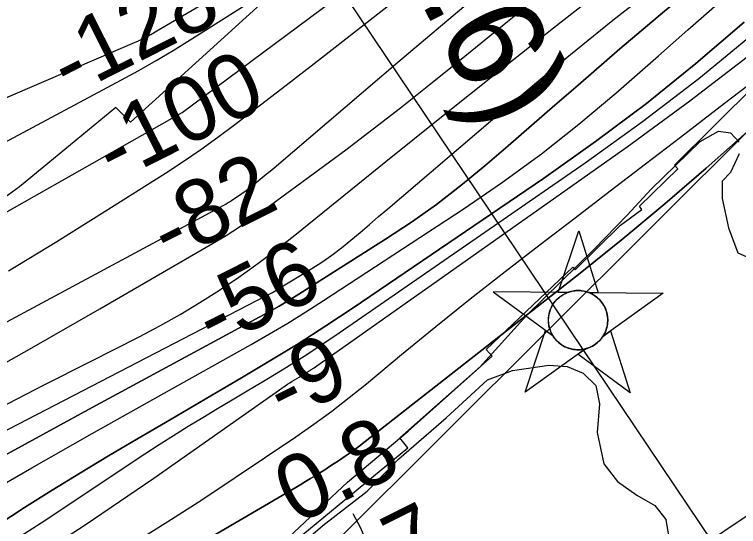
# Model space of a CAD drawing. Extents: x 3715084 to 3753216, y 488173 to 513963.
# Drawn here: x 3731429 to 3732175, y 498790 to 499318 of the extents above; entities that cross this region are included whole.
import ezdxf

# ---------------------------------------------------------------- set-up
doc = ezdxf.new("R2010")
doc.units = 0
for name, color, linetype in [('V-CHAN-NAID', 7, 'Continuous'), ('V-RIVR-EDGE', 7, 'Continuous'), ('V-RIVR-RANG', 7, 'Continuous'), ('V-ROAD-CNTR', 7, 'Continuous'), ('V-RRAP-FSHR', 7, 'Continuous'), ('V-RRAP-RVMT', 7, 'Continuous'), ('V-SITE-VEGE', 7, 'Continuous'), ('V-TOPO-DPTH', 7, 'Continuous'), ('V-TOPO-MAJR', 7, 'Continuous'), ('V-TOPO-MINR', 7, 'Continuous'), ('V-TOPO-WATR', 7, 'Continuous')]:
    doc.layers.add(name, color=color, linetype=linetype)

msp = doc.modelspace()

# ---------------------------------------------------------------- linework, layer by layer
at = {"layer": 'V-CHAN-NAID'}
for points in [[(3731998.934, 499031.306), (3731989.347, 499031.374), (3732010.473, 499094.858), (3732030.697, 499031.081), (3732021.11, 499031.14900000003), (3732019.5330000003, 499031.727), (3732017.438, 499032.347), (3732015.398, 499032.798), (3732013.362, 499033.106), (3732012.1950000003, 499033.22000000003), (3732010.661, 499033.30100000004), (3732008.9390000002, 499033.299), (3732007.569, 499033.229), (3732005.663, 499033.028), (3732004.2970000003, 499032.809), (3732002.5130000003, 499032.425), (3732000.983, 499032.005), (3731999.951, 499031.674)], [(3731998.934, 499031.306), (3731922.443, 499031.848), (3731984.008, 498986.449), (3731982.895, 498988.358), (3731982.085, 498989.98600000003), (3731981.2600000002, 498991.954), (3731980.5640000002, 498994.00800000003), (3731980.199, 498995.331), (3731979.838, 498996.957), (3731979.594, 498998.402), (3731979.406, 499000), (3731979.2970000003, 499001.73600000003), (3731979.285, 499003.31700000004), (3731979.392, 499005.391), (3731979.575, 499007.009), (3731979.967, 499009.212), (3731980.448, 499011.135), (3731981.051, 499013.022), (3731981.7060000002, 499014.701), (3731982.433, 499016.289), (3731983.247, 499017.824), (3731984.308, 499019.561), (3731985.339, 499021.031), (3731986.339, 499022.3), (3731987.341, 499023.446), (3731988.65, 499024.783), (3731989.701, 499025.748), (3731991.418, 499027.145), (3731992.63, 499028.015), (3731994.3170000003, 499029.085), (3731996.048, 499030.03), (3731997.494, 499030.71400000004)], [(3732021.11, 499031.14900000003), (3732097.602, 499030.606), (3732035.399, 498986.08400000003), (3732036.31, 498987.57300000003), (3732037.288, 498989.42), (3732038.003, 498991.005), (3732038.742, 498992.96), (3732039.287, 498994.745), (3732039.685, 498996.384), (3732040.046, 498998.39400000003), (3732040.2320000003, 498999.967), (3732040.356, 499002.173), (3732040.326, 499004.235), (3732040.1380000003, 499006.455), (3732039.872, 499008.213), (3732039.381, 499010.445), (3732038.741, 499012.585), (3732037.991, 499014.56700000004), (3732037.343, 499016.01), (3732036.336, 499017.92600000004), (3732035.274, 499019.648), (3732034.06, 499021.35000000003), (3732032.799, 499022.889), (3732031.5270000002, 499024.255), (3732029.895, 499025.787), (3732028.1520000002, 499027.199), (3732026.469, 499028.376), (3732024.582, 499029.50800000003), (3732023.11, 499030.26900000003)], [(3732017.3680000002, 498973.178), (3731955.165, 498928.656), (3731976.291, 498992.139), (3731984.008, 498986.449), (3731984.643, 498985.485), (3731986.026, 498983.626), (3731987.239, 498982.21), (3731988.705, 498980.707), (3731990.094, 498979.456), (3731991.548, 498978.3), (3731992.951, 498977.313), (3731994.629, 498976.277), (3731996.343, 498975.36600000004), (3731998.134, 498974.555), (3731999.58, 498973.999), (3732001.208, 498973.47000000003), (3732003.434, 498972.906), (3732004.966, 498972.619), (3732006.991, 498972.362), (3732008.528, 498972.25800000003), (3732010.389, 498972.23600000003), (3732012.078, 498972.314), (3732013.788, 498972.49), (3732015.69, 498972.80100000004)], [(3732035.399, 498986.08400000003), (3732043.1950000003, 498991.66500000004), (3732063.419, 498927.88800000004), (3732009.571, 498967.598), (3732017.3680000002, 498973.178), (3732019.034, 498973.65400000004), (3732020.646, 498974.21400000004), (3732022.804, 498975.128), (3732024.539, 498976.012), (3732026.4050000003, 498977.126), (3732028.144, 498978.338), (3732029.696, 498979.583), (3732030.983, 498980.751), (3732032.367, 498982.17100000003), (3732033.571, 498983.57300000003), (3732034.69, 498985.045)]]:
    msp.add_lwpolyline(points, close=True, dxfattribs=at)
msp.add_circle((3732009.820163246, 499002.7718519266), 30.540600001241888, dxfattribs=at)
at = {"layer": 'V-RIVR-EDGE'}
for points in [[(3731689.8314078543, 498758.2833762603), (3731772.267144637, 498835.5216719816), (3731834.831362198, 498888.19571232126), (3731908.2340504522, 498954.0501381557), (3731956.993808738, 499007.95896622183), (3732026.8004969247, 499076.223590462), (3732060.5046795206, 499110.9591943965), (3732085.184720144, 499137.91286621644), (3732135.733571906, 499187.01465730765), (3732154.370303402, 499197.7744534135), (3732166.972632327, 499195.94231157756), (3732175.953725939, 499186.31487779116)], [(3732175.9240374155, 499174.30841854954), (3732166.871691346, 499155.12035015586), (3732158.4449034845, 499146.13628769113), (3732158.400370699, 499128.1265988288), (3732164.929701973, 499098.0941220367), (3732174.47103904, 499072.2564838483), (3732192.461430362, 499064.4077525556)]]:
    msp.add_lwpolyline(points, dxfattribs=at)
at = {"layer": 'V-RIVR-RANG'}
msp.add_line((3732171.634, 498739.5240000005), (3731602.801, 499586.1890000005), dxfattribs=at)
at = {"layer": 'V-ROAD-CNTR'}
msp.add_lwpolyline([(3731869.65422165, 498539.2948953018), (3731864.162232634, 498549.95487398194), (3731854.753251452, 498570.33883321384), (3731844.896271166, 498591.65479058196), (3731838.012284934, 498602.94376800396), (3731835.38929018, 498607.3817591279), (3731833.8952931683, 498610.87875213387), (3731829.838301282, 498629.54371480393), (3731826.18430859, 498650.1526735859), (3731820.0663208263, 498676.32262124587), (3731813.5783338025, 498702.2205694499), (3731807.666345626, 498723.18452752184), (3731801.545357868, 498743.9584859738), (3731797.231366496, 498757.9214580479), (3731792.5453758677, 498772.2724293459), (3731786.0043889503, 498788.10939767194), (3731778.115404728, 498802.88936811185)], dxfattribs=at)
at = {"layer": 'V-RRAP-FSHR'}
for points in [[(3728004.355522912, 498122.759115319), (3728249.570755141, 498078.76397927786), (3728561.470915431, 498063.71117926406), (3728941.9278757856, 498053.3667312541), (3729895.3271726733, 498086.10810728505), (3730231.158212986, 498125.41537132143), (3730543.470021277, 498170.09453936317), (3730885.5146935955, 498262.3692274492), (3731364.1691580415, 498511.07834768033), (3731760.7561664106, 498774.8320759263), (3732302.403014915, 499315.13748442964), (3732839.9006154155, 499636.89057272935)], [(3732355.051, 498904.53500000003), (3732342.347, 498883.342), (3732313.9590000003, 498861.691), (3732243.934, 498823.59), (3732183.048, 498800.223), (3732137.92, 498769.938), (3732085.916, 498726.516), (3732043.611, 498687.15400000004), (3732005.186, 498656.417), (3732003.8310000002, 498655.46400000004)]]:
    msp.add_lwpolyline(points, dxfattribs=at)
at = {"layer": 'V-RRAP-RVMT'}
for p, q in [((3731723.8710000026, 499366.57600000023), (3731548.6950000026, 499207.10200000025)), ((3732109.2200000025, 499162.55100000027), (3732207.505000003, 499260.49800000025)), ((3731533.4840000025, 499222.06800000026), (3731434.2540000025, 499140.41800000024)), ((3731548.6950000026, 499207.10200000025), (3731533.4840000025, 499222.06800000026)), ((3732112.6070000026, 499158.91000000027), (3732109.2200000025, 499162.55100000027)), ((3732073.2726972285, 499120.2043080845), (3732112.6070000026, 499158.91000000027)), ((3731434.2540000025, 499140.41800000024), (3731344.696000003, 499075.39900000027)), ((3732053.559898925, 499100.8065447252), (3732075.6270000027, 499116.87500000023)), ((3732075.6270000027, 499116.87500000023), (3732073.2726972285, 499120.2043080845)), ((3732006.8580000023, 499054.851), (3732053.559898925, 499100.8065447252)), ((3731915.1590000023, 498972.56200000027), (3732004.270000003, 499057.41100000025)), ((3732004.270000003, 499057.41100000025), (3732006.858000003, 499054.85100000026)), ((3731921.4620000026, 498965.781), (3731915.1590000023, 498972.56200000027)), ((3731826.1310000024, 498881.44900000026), (3731921.4620000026, 498965.781)), ((3731834.363000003, 498871.06800000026), (3731826.1310000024, 498881.44900000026)), ((3731726.066000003, 498781.7350000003), (3731834.363000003, 498871.06800000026))]:
    msp.add_line(p, q, dxfattribs=at)
at = {"layer": 'V-SITE-VEGE'}
msp.add_lwpolyline([(3731707.025, 498756.777), (3731746.858, 498790.897), (3731792.383, 498826.28), (3731825.264, 498859.765), (3731873.951, 498902.101), (3731916.318, 498941.275), (3731942.238, 498950.74700000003), (3731979.534, 498956.422), (3731998.4960000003, 498955.15), (3732014.927, 498948.191), (3732028.198, 498935.545), (3732031.983, 498916.58), (3732029.444, 498886.87200000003), (3732036.386, 498854.632), (3732050.286, 498836.299), (3732070.508, 498822.38300000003), (3732088.836, 498811.631), (3732100.2060000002, 498797.088), (3732102.7290000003, 498782.549)], dxfattribs=at)
at = {"layer": 'V-TOPO-DPTH'}
for points in [[(3732192.8321344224, 499396.94608609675), (3732145.470158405, 499359.7320163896), (3732098.9486231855, 499321.47250100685), (3732052.987381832, 499282.5160218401), (3732010.072803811, 499245.3127053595), (3731985.9830099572, 499224.4421264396), (3731961.8844900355, 499203.5816344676), (3731937.7728810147, 499182.73627291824), (3731913.652545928, 499161.900998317), (3731889.1014387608, 499141.64569476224), (3731863.987293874, 499122.1500922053), (3731838.0285924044, 499103.79404114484), (3731811.506853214, 499086.197691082), (3731722.0839605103, 499029.70202496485), (3731712.0017979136, 499023.47431658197), (3731701.8387850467, 499017.3846931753), (3731691.5544967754, 499011.50219723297), (3731681.189358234, 499005.75778626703), (3731505.287765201, 498910.5887366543), (3731407.063469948, 498857.0881025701)], [(3732192.8321344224, 499396.94608609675), (3732145.470158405, 499359.7320163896), (3732098.9486231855, 499321.47250100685), (3732052.987381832, 499282.5160218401), (3732010.072803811, 499245.3127053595), (3731985.9830099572, 499224.4421264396), (3731961.8844900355, 499203.5816344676), (3731937.7728810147, 499182.73627291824), (3731913.652545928, 499161.900998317), (3731889.1014387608, 499141.64569476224), (3731863.987293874, 499122.1500922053), (3731838.0285924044, 499103.79404114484), (3731811.506853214, 499086.197691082), (3731722.0839605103, 499029.70202496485), (3731712.0017979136, 499023.47431658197), (3731701.8387850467, 499017.3846931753), (3731691.5544967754, 499011.50219723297), (3731681.189358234, 499005.75778626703), (3731505.287765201, 498910.5887366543), (3731407.063469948, 498857.0881025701)], [(3731384.6007912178, 498814.7238095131), (3731446.752551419, 498850.36080582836), (3731509.0578856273, 498885.72861791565), (3731571.465602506, 498920.91697385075), (3731672.887099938, 498977.8143518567), (3731691.816059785, 498988.6907619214), (3731710.5898538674, 498999.82282742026), (3731729.1308993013, 499011.3383760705), (3731747.51677897, 499023.10958015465), (3731891.2776887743, 499117.2468652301), (3731932.0717315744, 499145.2017952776), (3731972.028830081, 499174.25825281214), (3732010.7305121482, 499204.96700157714), (3732048.595249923, 499236.7772778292), (3732062.467725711, 499248.9379169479), (3732092.7594892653, 499275.5047564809), (3732123.0426389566, 499302.081406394), (3732153.3128678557, 499328.6727718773), (3732183.5744828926, 499355.27394774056)], [(3731384.6007912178, 498814.7238095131), (3731446.752551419, 498850.36080582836), (3731509.0578856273, 498885.72861791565), (3731571.465602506, 498920.91697385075), (3731672.887099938, 498977.8143518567), (3731691.816059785, 498988.6907619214), (3731710.5898538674, 498999.82282742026), (3731729.1308993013, 499011.3383760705), (3731747.51677897, 499023.10958015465), (3731891.2776887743, 499117.2468652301), (3731932.0717315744, 499145.2017952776), (3731972.028830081, 499174.25825281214), (3732010.7305121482, 499204.96700157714), (3732048.595249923, 499236.7772778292), (3732062.467725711, 499248.9379169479), (3732092.7594892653, 499275.5047564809), (3732123.0426389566, 499302.081406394), (3732153.3128678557, 499328.6727718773), (3732183.5744828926, 499355.27394774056)], [(3732180.84515782, 499310.00770743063), (3732131.056996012, 499267.39537584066), (3732080.21590364, 499226.1337401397), (3732027.795415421, 499186.89814827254), (3731974.321996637, 499149.01325229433), (3731778.04483976, 499015.6626121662), (3731749.7543801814, 498996.87015104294), (3731721.212436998, 498978.4770160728), (3731692.2932684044, 498960.6828703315), (3731663.1226162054, 498943.2880507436), (3731643.1439167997, 498931.65512568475), (3731613.817081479, 498914.5245875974), (3731584.5220994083, 498897.3399209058), (3731555.274897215, 498880.07406130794), (3731526.0595482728, 498862.7540731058), (3731496.9720034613, 498845.22620367), (3731468.0229672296, 498827.4753582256), (3731439.2816938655, 498809.3900487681), (3731410.6789290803, 498791.0817633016)], [(3732180.84515782, 499310.00770743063), (3732131.056996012, 499267.39537584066), (3732080.21590364, 499226.1337401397), (3732027.795415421, 499186.89814827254), (3731974.321996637, 499149.01325229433), (3731778.04483976, 499015.6626121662), (3731749.7543801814, 498996.87015104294), (3731721.212436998, 498978.4770160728), (3731692.2932684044, 498960.6828703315), (3731663.1226162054, 498943.2880507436), (3731643.1439167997, 498931.65512568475), (3731613.817081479, 498914.5245875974), (3731584.5220994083, 498897.3399209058), (3731555.274897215, 498880.07406130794), (3731526.0595482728, 498862.7540731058), (3731496.9720034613, 498845.22620367), (3731468.0229672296, 498827.4753582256), (3731439.2816938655, 498809.3900487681), (3731410.6789290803, 498791.0817633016)], [(3731430.267337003, 498745.24601005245), (3731501.9449256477, 498791.82197907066), (3731572.685340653, 498839.890202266), (3731708.1364632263, 498935.0245384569), (3731710.4619972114, 498936.6241758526), (3731712.8076701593, 498938.1930568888), (3731715.183551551, 498939.7158033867), (3731717.5795719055, 498941.2077935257), (3731719.991397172, 498942.6755637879), (3731722.404138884, 498944.14182443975), (3731724.8182552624, 498945.6058206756), (3731727.233288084, 498947.06830730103), (3731728.5896916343, 498947.88884369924), (3731731.6626691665, 498949.79248376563), (3731734.707749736, 498951.73876958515), (3731737.710984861, 498953.74902403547), (3731740.6863230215, 498955.8019242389), (3732060.388669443, 499181.41608414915), (3732125.079654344, 499228.85100412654), (3732188.5586806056, 499277.8000096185)], [(3731430.267337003, 498745.24601005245), (3731501.9449256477, 498791.82197907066), (3731572.685340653, 498839.890202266), (3731708.1364632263, 498935.0245384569), (3731710.4619972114, 498936.6241758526), (3731712.8076701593, 498938.1930568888), (3731715.183551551, 498939.7158033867), (3731717.5795719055, 498941.2077935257), (3731719.991397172, 498942.6755637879), (3731722.404138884, 498944.14182443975), (3731724.8182552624, 498945.6058206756), (3731727.233288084, 498947.06830730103), (3731728.5896916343, 498947.88884369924), (3731731.6626691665, 498949.79248376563), (3731734.707749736, 498951.73876958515), (3731737.710984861, 498953.74902403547), (3731740.6863230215, 498955.8019242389), (3732060.388669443, 499181.41608414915), (3732125.079654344, 499228.85100412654), (3732188.5586806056, 499277.8000096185)], [(3732184.0655974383, 499197.18875808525), (3732141.9862572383, 499159.6307915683), (3732099.366319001, 499122.71110202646), (3732055.9354837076, 499086.74882794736), (3732011.9640503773, 499051.42483084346), (3731790.447993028, 498877.49218061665), (3731783.7222243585, 498872.35138048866), (3731776.9108025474, 498867.32999287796), (3731769.970901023, 498862.48772404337), (3731762.945346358, 498857.7648677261), (3731758.476137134, 498854.84429656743), (3731753.611226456, 498851.6864820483), (3731748.7334905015, 498848.5487405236), (3731743.836516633, 498845.441108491), (3731738.92671749, 498842.3535494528), (3731733.994358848, 498839.3024426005), (3731729.044750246, 498836.2798589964), (3731724.0692667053, 498833.3000602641), (3731719.076533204, 498830.34878477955), (3731528.6333635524, 498718.880158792)]]:
    msp.add_lwpolyline(points, dxfattribs=at)
at = {"layer": 'V-TOPO-MAJR'}
for points in [[(3731335.931092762, 499066.49062621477), (3731601.9, 499217.08), (3731840.8801341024, 499394.9306495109), (3731920.6436163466, 499454.33798377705), (3732000.377158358, 499513.7854435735)], [(3731338.438875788, 498846.8191364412), (3731688.012711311, 499027.7377901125), (3731691.437224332, 499029.55615927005), (3731694.8350014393, 499031.4220211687), (3731698.1926746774, 499033.3591221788), (3731701.5236120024, 499035.34371593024), (3731735.2957322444, 499055.951059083), (3731745.8080933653, 499062.71032409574), (3731756.0909330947, 499069.7868532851), (3731766.0294907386, 499077.33927873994), (3731775.73852699, 499085.2089683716), (3731785.2714384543, 499093.3214640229), (3731794.800217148, 499101.4388072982), (3731804.322796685, 499109.563422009), (3731813.8412434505, 499117.6928843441), (3731919.428879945, 499207.9423082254), (3731982.2539455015, 499260.55376094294), (3732045.7662304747, 499312.304215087), (3732110.3093445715, 499362.763171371), (3732175.539678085, 499412.36112908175)]]:
    msp.add_lwpolyline(points, dxfattribs=at)
at = {"layer": 'V-TOPO-MINR'}
for points in [[(3731418.6115811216, 499185.9903395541), (3731539.3417904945, 499250.53052315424), (3731557.2961822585, 499260.39148691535), (3731575.0947494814, 499270.51922923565), (3731592.6595798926, 499281.0471393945), (3731610.0685857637, 499291.8418281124), (3731709.6843329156, 499355.18188153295), (3731776.231841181, 499398.6424204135), (3731842.043873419, 499443.1621750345), (3731906.7526916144, 499489.27075326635), (3731970.726033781, 499536.43854723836), (3732097.5584063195, 499632.35789194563), (3732115.595816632, 499646.2020661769), (3732133.498951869, 499660.21529411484), (3732151.200674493, 499674.48210261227), (3732168.7681220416, 499688.9179648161), (3732186.2520773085, 499703.4598055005)], [(3731422.704916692, 499053.57361793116), (3731472.7660384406, 499084.0579859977), (3731522.503361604, 499115.08388729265), (3731584.5499506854, 499154.4877315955), (3731602.8503376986, 499166.46170375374), (3731620.923584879, 499178.75991888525), (3731638.656122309, 499191.5444984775), (3731656.161519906, 499204.653321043), (3731708.9670352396, 499245.32776867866), (3731745.2860989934, 499273.41608654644), (3731781.531796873, 499301.59838314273), (3731817.6674459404, 499329.9216478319), (3731853.729729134, 499358.3388912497), (3731889.8512083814, 499386.6781433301), (3731926.1249606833, 499414.8194554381), (3731962.6271225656, 499442.6638575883), (3731999.281557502, 499470.3103197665), (3732059.023132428, 499514.98894035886), (3732105.472857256, 499549.7672732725), (3732151.896798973, 499584.5799491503), (3732198.2820660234, 499619.44413947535)], [(3731333.8479092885, 498954.17198305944), (3731644.673746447, 499121.3546100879), (3731646.6838153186, 499122.47860115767), (3731648.6676973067, 499123.6454902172), (3731650.612298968, 499124.87672626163), (3731652.5307137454, 499126.1508602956), (3731663.357224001, 499133.5998652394), (3731667.681992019, 499136.6638493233), (3731671.9481584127, 499139.805171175), (3731676.126422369, 499143.06249967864), (3731680.2460847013, 499146.39716595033), (3731684.3153101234, 499149.79753859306), (3731688.3759906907, 499153.2080464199), (3731692.4238539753, 499156.63375702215), (3731696.463172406, 499160.0696028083), (3731823.9940856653, 499268.96021531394), (3731892.09187303, 499326.48552571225), (3731960.5887855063, 499383.5263702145), (3732029.6843856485, 499439.840515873), (3732099.1791109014, 499495.6701956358), (3732209.7160100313, 499583.51518125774)], [(3731371.5155886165, 498932.0869067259), (3731444.4025640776, 498972.86938920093), (3731516.911742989, 499014.33836621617), (3731632.983953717, 499081.80999112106), (3731647.030416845, 499090.27693732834), (3731660.8864823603, 499099.03476759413), (3731674.4569514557, 499108.2289239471), (3731687.8370229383, 499117.7139643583), (3731742.0079283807, 499157.42549097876), (3731770.4700721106, 499178.5977578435), (3731798.730739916, 499200.03184990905), (3731826.689193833, 499221.8586797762), (3731854.446171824, 499243.9473348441), (3731882.039274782, 499266.248118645), (3731909.615444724, 499288.56979716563), (3731937.1662151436, 499310.9228177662), (3731964.7000525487, 499333.29673308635), (3732015.2427745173, 499374.41533279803), (3732068.182795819, 499417.17851999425), (3732121.319491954, 499459.6941362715), (3732174.751200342, 499501.8383961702), (3732228.3795835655, 499543.73508514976)], [(3731412.8027772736, 498912.1160407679), (3731459.680268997, 498935.93034551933), (3731506.5527023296, 498959.7546114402), (3731557.5216226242, 498985.67125645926), (3731578.7043641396, 498996.89158403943), (3731599.6192145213, 499008.57326971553), (3731620.1322282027, 499020.94699253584), (3731640.3773507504, 499033.782073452), (3731660.211486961, 499047.25083940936), (3731679.7667905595, 499061.1011940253), (3731698.9038452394, 499075.5239316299), (3731717.7620673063, 499090.32825789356), (3731811.615800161, 499166.2776745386), (3731869.1084505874, 499212.5642536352), (3731926.754856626, 499258.6575462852), (3731984.6318960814, 499304.46090926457), (3732042.6626911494, 499350.07098579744), (3732099.5328947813, 499394.53843687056), (3732129.2447193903, 499417.76878106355), (3732158.9576212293, 499440.99774723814), (3732188.6721389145, 499464.2246463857)], [(3731407.063469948, 498857.0881025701), (3731505.287765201, 498910.5887366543), (3731681.189358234, 499005.75778626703), (3731691.5544967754, 499011.50219723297), (3731701.8387850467, 499017.3846931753), (3731712.0017979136, 499023.47431658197), (3731722.0839605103, 499029.70202496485), (3731811.506853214, 499086.197691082), (3731838.0285924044, 499103.79404114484), (3731863.987293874, 499122.1500922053), (3731889.1014387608, 499141.64569476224), (3731913.652545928, 499161.900998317), (3731937.7728810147, 499182.73627291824), (3731961.8844900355, 499203.5816344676), (3731985.9830099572, 499224.4421264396), (3732010.072803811, 499245.3127053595), (3732052.987381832, 499282.5160218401), (3732098.9486231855, 499321.47250100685), (3732145.470158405, 499359.7320163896), (3732192.8321344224, 499396.94608609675)], [(3731225.5262661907, 499148.6630740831), (3731550.406883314, 499288.0918371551), (3731556.9055609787, 499291.0361476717), (3731563.317860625, 499294.14966056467), (3731569.6005932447, 499297.51697702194), (3731575.7969478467, 499301.05349585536), (3731638.437985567, 499338.4858116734), (3731661.1427240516, 499352.7969287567), (3731683.3555769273, 499367.8002498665)], [(3731384.6007912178, 498814.7238095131), (3731446.752551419, 498850.36080582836), (3731509.0578856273, 498885.72861791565), (3731571.465602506, 498920.91697385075), (3731672.887099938, 498977.8143518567), (3731691.816059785, 498988.6907619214), (3731710.5898538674, 498999.82282742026), (3731729.1308993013, 499011.3383760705), (3731747.51677897, 499023.10958015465), (3731891.2776887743, 499117.2468652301), (3731932.0717315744, 499145.2017952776), (3731972.028830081, 499174.25825281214), (3732010.7305121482, 499204.96700157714), (3732048.595249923, 499236.7772778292), (3732062.467725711, 499248.9379169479), (3732092.7594892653, 499275.5047564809), (3732123.0426389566, 499302.081406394), (3732153.3128678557, 499328.6727718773), (3732183.5744828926, 499355.27394774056)], [(3731410.6789290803, 498791.0817633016), (3731439.2816938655, 498809.3900487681), (3731468.0229672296, 498827.4753582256), (3731496.9720034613, 498845.22620367), (3731526.0595482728, 498862.7540731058), (3731555.274897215, 498880.07406130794), (3731584.5220994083, 498897.3399209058), (3731613.817081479, 498914.5245875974), (3731643.1439167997, 498931.65512568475), (3731663.1226162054, 498943.2880507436), (3731692.2932684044, 498960.6828703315), (3731721.212436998, 498978.4770160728), (3731749.7543801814, 498996.87015104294), (3731778.04483976, 499015.6626121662), (3731974.321996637, 499149.01325229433), (3732027.795415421, 499186.89814827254), (3732080.21590364, 499226.1337401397), (3732131.056996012, 499267.39537584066), (3732180.84515782, 499310.00770743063)], [(3731387.5971735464, 498749.7618550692), (3731456.4299424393, 498793.86630970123), (3731563.2908910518, 498864.74475831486), (3731578.0976820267, 498874.42647048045), (3731592.9871711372, 498883.97737891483), (3731608.000707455, 498893.3320817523), (3731623.096941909, 498902.5559808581), (3731638.2638675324, 498911.66727826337), (3731653.4423168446, 498920.75929610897), (3731668.6380516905, 498929.82239461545), (3731683.8453102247, 498938.8662135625), (3731690.727055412, 498942.94995118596), (3731709.2607506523, 498954.2129625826), (3731727.630508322, 498965.7314243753), (3731745.754359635, 498977.6330617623), (3731763.714273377, 498989.7901495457), (3732016.9840800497, 499165.13494708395), (3732076.244049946, 499207.8412688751), (3732134.3645336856, 499251.99026624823), (3732190.775788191, 499298.3032769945)], [(3731430.267337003, 498745.24601005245), (3731501.9449256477, 498791.82197907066), (3731572.685340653, 498839.890202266), (3731708.1364632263, 498935.0245384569), (3731710.4619972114, 498936.6241758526), (3731712.8076701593, 498938.1930568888), (3731715.183551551, 498939.7158033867), (3731717.5795719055, 498941.2077935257), (3731719.991397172, 498942.6755637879), (3731722.404138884, 498944.14182443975), (3731724.8182552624, 498945.6058206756), (3731727.233288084, 498947.06830730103), (3731728.5896916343, 498947.88884369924), (3731731.6626691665, 498949.79248376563), (3731734.707749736, 498951.73876958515), (3731737.710984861, 498953.74902403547), (3731740.6863230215, 498955.8019242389), (3732060.388669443, 499181.41608414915), (3732125.079654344, 499228.85100412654), (3732188.5586806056, 499277.8000096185)], [(3731552.0082783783, 498773.1738242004), (3731587.1963693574, 498795.05737033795), (3731621.9978008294, 498817.5507406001), (3731656.5414592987, 498840.4506602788), (3731718.819055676, 498882.521879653), (3731737.506974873, 498895.55016768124), (3731755.927589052, 498908.93518948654), (3731773.9472457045, 498922.85531195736), (3731791.6995973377, 498937.1321682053), (3731828.005821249, 498967.21921029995), (3731863.2669264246, 498996.09572177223), (3731898.748312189, 499024.6956727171), (3731934.5601188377, 499052.8807828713), (3731970.592206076, 499080.7893324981), (3732006.786034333, 499108.4949938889), (3732042.975167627, 499136.2067848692), (3732079.1572584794, 499163.9277702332), (3732115.3346543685, 499191.65488518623), (3732160.7770082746, 499226.492023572), (3732216.6444118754, 499269.3228708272)]]:
    msp.add_lwpolyline(points, dxfattribs=at)
at = {"layer": 'V-TOPO-WATR'}
msp.add_lwpolyline([(3731528.6333635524, 498718.880158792), (3731719.076533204, 498830.34878477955), (3731724.0692667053, 498833.3000602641), (3731729.044750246, 498836.2798589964), (3731733.994358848, 498839.3024426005), (3731738.92671749, 498842.3535494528), (3731743.836516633, 498845.441108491), (3731748.7334905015, 498848.5487405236), (3731753.611226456, 498851.6864820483), (3731758.476137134, 498854.84429656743), (3731762.945346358, 498857.7648677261), (3731769.970901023, 498862.48772404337), (3731776.9108025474, 498867.32999287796), (3731783.7222243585, 498872.35138048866), (3731790.447993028, 498877.49218061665), (3732011.9640503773, 499051.42483084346), (3732055.9354837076, 499086.74882794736), (3732099.366319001, 499122.71110202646), (3732141.9862572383, 499159.6307915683), (3732184.0655974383, 499197.18875808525)], dxfattribs=at)

# ---------------------------------------------------------------- texts
at = {"layer": 'V-CHAN-NAID'}
msp.add_text('POYDRAS "82" (81.6)', height=100.00000199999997, rotation=297.16950570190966, dxfattribs=at).set_placement((3731314.1228443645, 500370.0896584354))
at = {"layer": 'V-RIVR-RANG'}
for s, rotation, p in [('-128', 26.73205555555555, (3731485.2804223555, 499232.80053612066)), ('-100', 26.73205555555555, (3731531.6905295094, 499144.2091069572)), ('-82', 26.73205555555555, (3731588.466453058, 499060.8374087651)), ('-56', 26.73205555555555, (3731634.6399734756, 498972.1263266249)), ('-9', 26.448325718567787, (3731707.1786982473, 498896.9660392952)), ('0.8', 26.448325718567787, (3731719.3480426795, 498791.33012359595)), ('8.7', 26.448325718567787, (3731764.1090426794, 498701.90712359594))]:
    msp.add_text(s, height=66.99999999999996, rotation=rotation, dxfattribs=at).set_placement(p)

doc.saveas('drawing.dxf')
